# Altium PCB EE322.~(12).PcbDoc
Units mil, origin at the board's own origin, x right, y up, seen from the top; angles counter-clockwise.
Board outline 6000 x 4000 mil, 2 copper layers (Top Layer, Bottom Layer); 45 components, 23 nets, 107 pads, 0 vias.
Unrouted connection lines stored in the file: 78.
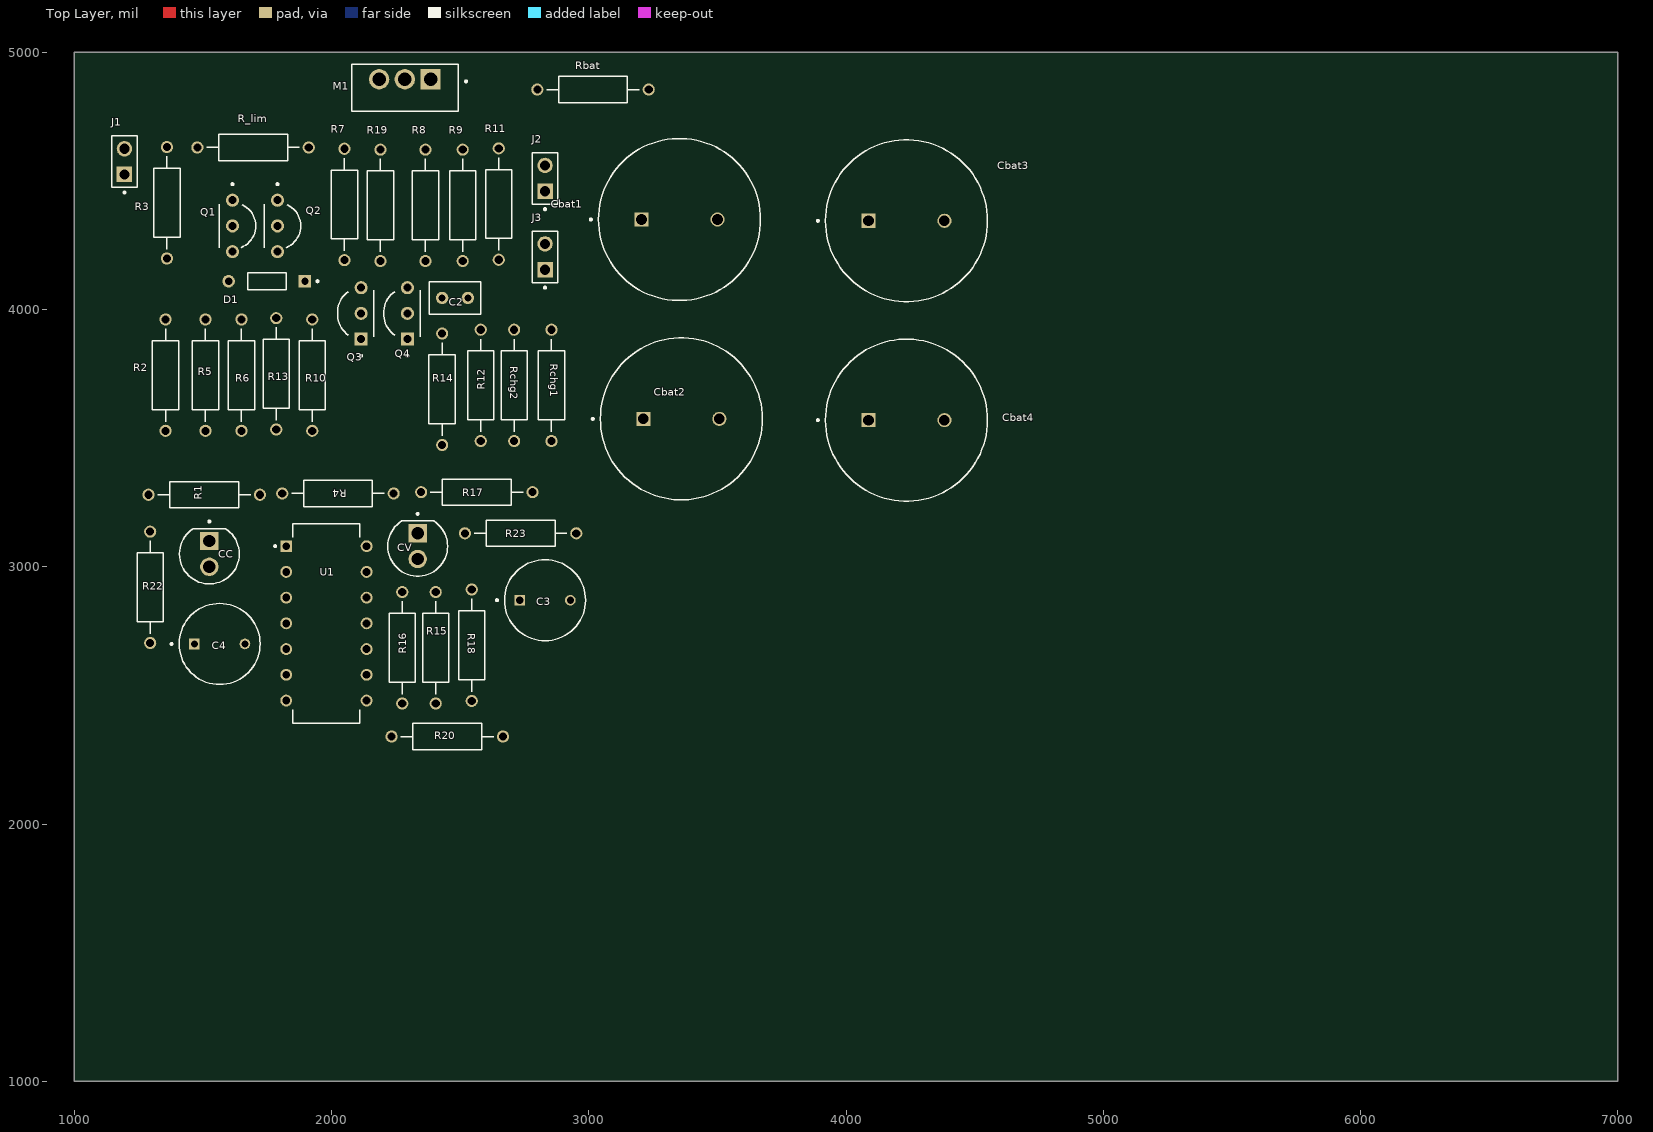
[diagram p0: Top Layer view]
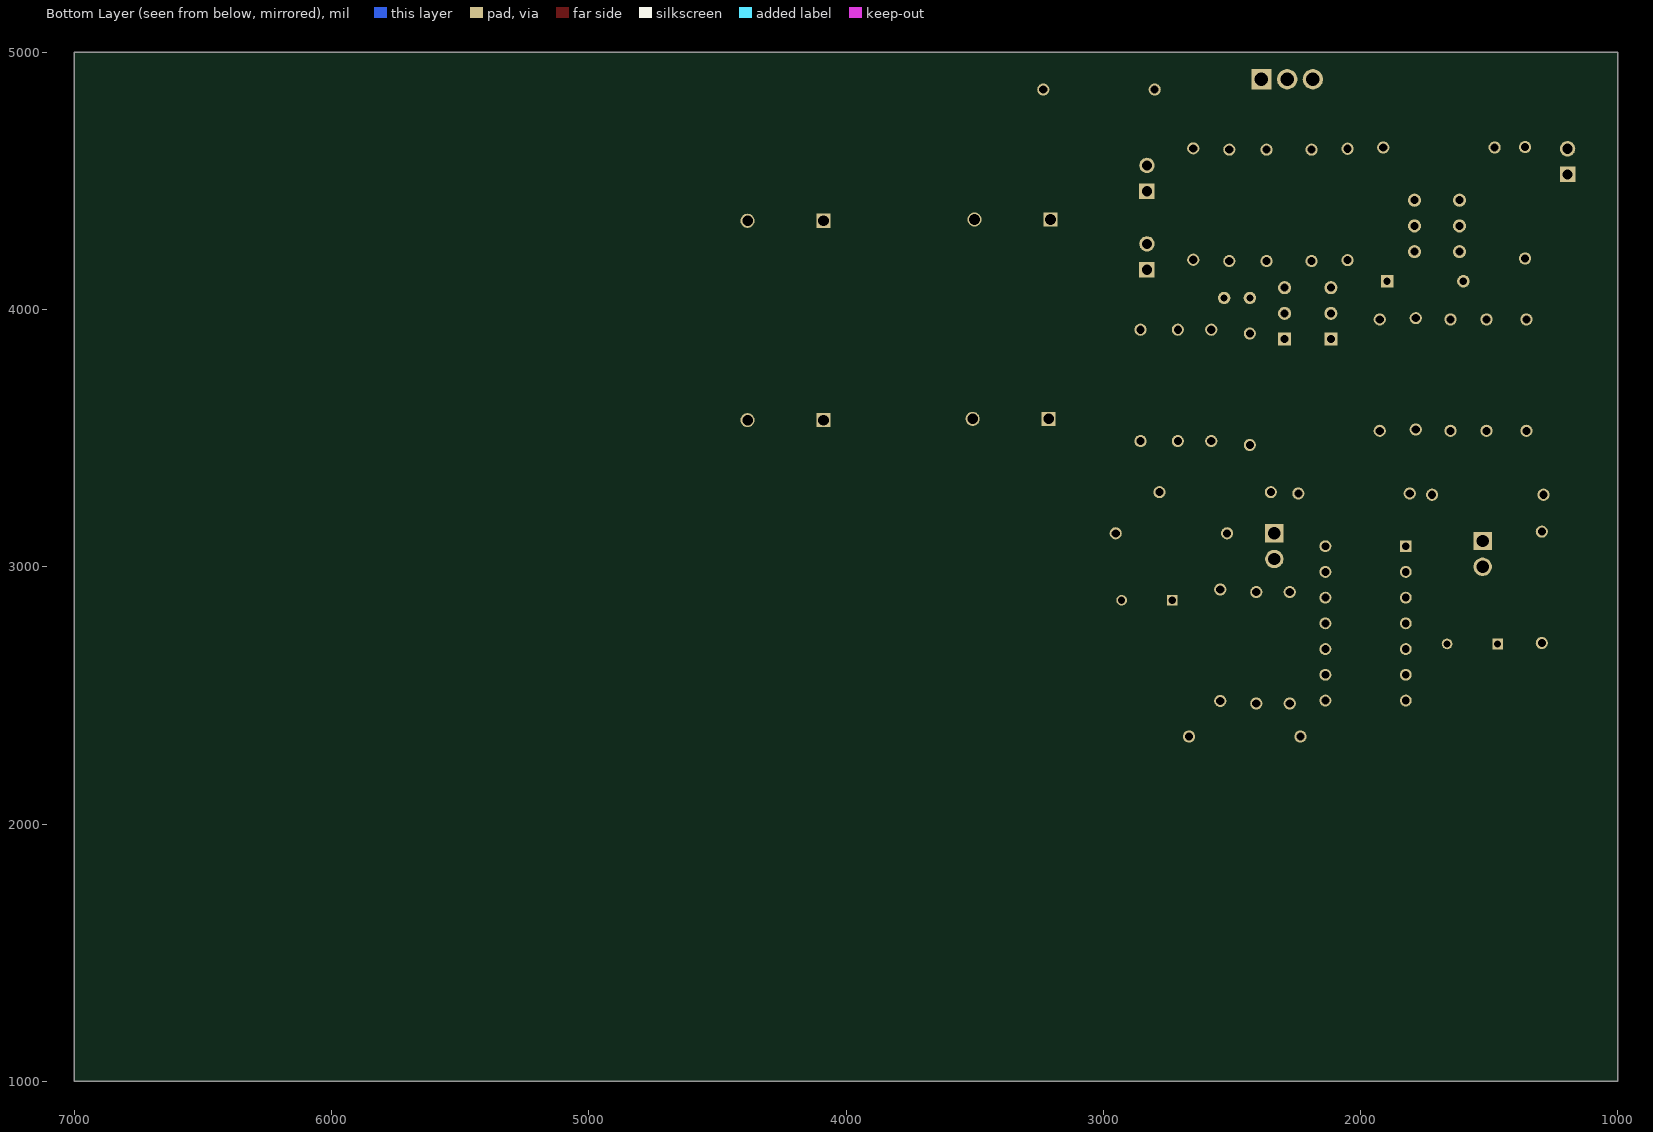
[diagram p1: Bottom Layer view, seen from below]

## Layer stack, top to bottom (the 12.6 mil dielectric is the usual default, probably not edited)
Top Solder: solder mask 0.4, Solder Resist, Dk 3.5
Top Layer: signal copper 1.4
Dielectric 1: dielectric 12.6, FR-4, Dk 4.8
Bottom Layer: signal copper 1.4
Bottom Solder: solder mask 0.4, Solder Resist, Dk 3.5

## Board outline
1000,1000 7000,1000 7000,5000 1000,5000

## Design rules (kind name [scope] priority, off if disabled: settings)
Clearance [All] p1: gap=10 ignorepadtopadclearanceinfootprint=FALSE
Height [All] p1: minheight=0 maxheight=1500 prefheight=500
PolygonConnect [All] p1: connectstyle=Relief reliefconductorwidth=10 reliefentries=4 polygonreliefangle="90 Angle" airgapwidth=10
RoutingVias [All] p1: holewidth=28 width=50 viastyle="Through Hole" minholewidth=28 minwidth=50 maxholewidth=28 maxwidth=50
SilkToSolderMaskClearance [IsPad] p1: minsilkscreentomaskgap=9 clearancetoexposedcopper=TRUE
SolderMaskExpansion [All] p1: expansion=0 istentingtop=FALSE
Width [All] p1: maxlimit=40 minlimit=20 preferedwidth=20
28 further rules are at their usual default settings.

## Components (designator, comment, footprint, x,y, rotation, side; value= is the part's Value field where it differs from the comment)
C2 "" CAPRR254W50L508T317H508 2480,4045 r0 top
C3 "ECEA1HKA330Q" CAPPRD500W45D800H700 2830,2870 r0 top
C4 "ECEA1HKA330Q" CAPPRD500W45D800H700 1565,2700 r0 top
Cbat1 "" CAPPRD750W80D1600H3150 3352.64,4350 r0 top
Cbat2 "" CAPPRD750W80D1600H3150 3360,3575 r0 top
Cbat3 "" CAPPRD750W80D1600H3150 4235,4345 r0 top
Cbat4 "" CAPPRD750W80D1600H3150 4235,3570 r0 top
CC "" LEDRD254W57D500H1070 1525,3050 r270 top
CV "" LEDRD254W57D500H1070 2335,3080 r270 top
D1 "1N4148" DIOAD753W49L380D172B 1748.37,4110 r180 top
J1 "" CONNFLY_DS1021-1X2SF11-B 1195,4575 r90 top
J2 "" CONNFLY_DS1021-1X2SF11-B 2830,4510 r90 top
J3 "" CONNFLY_DS1021-1X2SF11-B 2830,4205 r90 top
M1 "" TO254P1052X465X1989-3 2385,4895 r180 top
Q1 "" TO92254P460H750-3#1 1615,4325 r270 top
Q2 "" TO92254P460H750-3#1 1790,4325 r270 top
Q3 "" TO92254P460H750-3#2 2115,3985 r90 top
Q4 "" TO92254P460H750-3#2 2295,3985 r90 top
R1 "" RESAD1100W55L680D260 1505,3280 r180 top
R2 "" RESAD1100W55L680D260 1355,3745 r90 top
R3 "" RESAD1100W55L680D260 1360,4415 r90 top
R4 "" RESAD1100W55L680D260 2025,3285 r180 top
R5 "" RESAD1100W55L680D260 1510,3745 r90 top
R6 "" RESAD1100W55L680D260 1650,3745 r90 top
R7 "" RESAD1100W55L680D260 2050,4408.46 r90 top
R8 "" RESAD1100W55L680D260 2365,4405 r90 top
R9 "" RESAD1100W55L680D260 2510,4405 r90 top
R10 "" RESAD1100W55L680D260 1925,3745 r270 top
R11 "" RESAD1100W55L680D260 2650,4410 r90 top
R12 "" RESAD1100W55L680D260 2580,3705 r90 top
R13 "" RESAD1100W55L680D260 1785,3750 r90 top
R14 "" RESAD1100W55L680D260 2430,3690 r270 top
R15 "MFR-25FBF52-10K" RESAD1100W55L680D260 2405,2685 r90 top
R16 "MFR-25FBF52-10K" RESAD1100W55L680D260 2275,2685 r270 top
R17 "MFR-25FBF52-10K" RESAD1100W55L680D260 2565,3290 r180 top
R18 "MFR-25FBF52-10K" RESAD1100W55L680D260 2545,2695 r90 top
R19 "" RESAD1100W55L680D260 2190,4405 r90 top
R20 "MFR-25FBF52-10K" RESAD1100W55L680D260 2450,2340 r0 top
R22 "" RESAD1100W55L680D260 1295,2920 r90 top
R23 "" RESAD1100W55L680D260 2735,3130 r0 top
R_lim "" RESAD1100W55L680D260 1695,4630 r0 top
Rbat "" RESAD1100W55L680D260 3016.54,4855 r180 top
Rchg1 "" RESAD1100W55L680D260 2855,3705 r270 top
Rchg2 "" RESAD1100W55L680D260 2710,3705 r270 top
U1 "LM339AN" DIP794W45P254L1969H508Q14 1980,2780 r0 top

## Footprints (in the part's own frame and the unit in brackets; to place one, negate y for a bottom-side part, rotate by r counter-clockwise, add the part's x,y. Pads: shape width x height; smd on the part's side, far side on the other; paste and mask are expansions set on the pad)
CAPPRD500W45D800H700 [mm]
  round 1.05 hole 0.7: N(2.5,0)
  rect 1.05x1.05 / inner round 1.05 / far side rect 1.05x1.05 hole 0.7: P(-2.5,0)
  silkscreen extent -4.85,-4 4,4, body extent -4,-4 4,4, height 7
CAPPRD750W80D1600H3150 [mm]
  round 1.4 hole 1.05: N(3.75,0)
  rect 1.4x1.4 hole 1.05: P(-3.75,0)
  silkscreen extent -8.85,-8 8,8, body extent -8,-8 8,8, height 31.5
CAPRR254W50L508T317H508 [mm]
  round 1.218 hole 0.71: 1(-1.27,0) 2(1.27,0)
  silkscreen extent -2.54,-1.59 2.54,1.59
CONNFLY_DS1021-1X2SF11-B [mm]
  rect 1.53x1.53 / inner round 1.53 / far side rect 1.53x1.53 hole 1.02 mask+0.102: 1(-1.27,0)
  round 1.53 hole 1.02 mask+0.102: 2(1.27,0)
  silkscreen extent -3.15,-1.25 2.54,1.25, body extent -2.54,-1.25 2.54,1.25, height 8.6
DIOAD753W49L380D172B [mm]
  round 1.238 hole 0.73 mask+0.102: A(3.768,0)
  rect 1.238x1.238 / inner round 1.238 / far side rect 1.238x1.238 hole 0.73 mask+0.102: K(-3.768,0)
  silkscreen extent -5.1,-0.86 1.9,0.86
DIP794W45P254L1969H508Q14 [mm]
  rect 1.17x1.17 / inner round 1.17 / far side rect 1.17x1.17 hole 0.77 mask+0.102: 1(-3.97,7.62)
  round 1.17 hole 0.77 mask+0.102: 2(-3.97,5.08) 3(-3.97,2.54) 4(-3.97,0) 5(-3.97,-2.54) 6(-3.97,-5.08) 7(-3.97,-7.62) 8(3.97,-7.62) 9(3.97,-5.08) 10(3.97,-2.54) 11(3.97,0) 12(3.97,2.54) 13(3.97,5.08) 14(3.97,7.62)
  silkscreen extent -5.15,-9.84 3.3,9.84, body extent -3.94,-9.65 3.94,9.65, height 5.08
LEDRD254W57D500H1070 [mm]
  round 1.815 hole 1.21: A(1.27,0)
  rect 1.815x1.815 / inner round 1.815 / far side rect 1.815x1.815 hole 1.21: C(-1.27,0)
  silkscreen extent -3.3,-2.96 2.96,2.96, body extent -2.6,-2.95 2.95,2.95, height 9.1
RESAD1100W55L680D260 [mm]
  round 1.2 hole 0.8: 1(-5.5,0) 2(5.5,0)
  silkscreen extent -4.58,-1.3 4.58,1.3, body extent -5.77,-1.2 5.77,1.2, height 2.4
TO254P1052X465X1989-3 [mm]
  rect 2.01x2.01 / inner round 2.01 / far side rect 2.01x2.01 hole 1.34: 1(0,0)
  round 2.01 hole 1.34: 2(2.54,0) 3(5.08,0)
  silkscreen extent -3.6,-1.5 7.8,3.16, body extent -5.12,-1.54 5.12,2.91, height 19.89
TO92254P460H750-3#1 [mm]
  round 1.298 hole 0.79 mask+0.102: 1(-2.54,0) 2(0,0) 3(2.54,0)
  silkscreen extent -4.22,-1.3 2.15,2.3, body extent -2.74,-1.27 2.74,2.33, height 8.09
TO92254P460H750-3#2 [mm]
  rect 1.298x1.298 / inner round 1.298 / far side rect 1.298x1.298 hole 0.79 mask+0.102: 1(-2.54,0)
  round 1.298 hole 0.79 mask+0.102: 2(0,0) 3(2.54,0)
  silkscreen extent -4.29,-1.27 2.3,2.33, body extent -2.74,-1.27 2.74,2.33, height 8.09

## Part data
C2: library part SR291C104KAR, "SR Series 5.08 x 5.08 mm 100 nF 100 V Â±10 % Tol. X7R Radial Lead/SkyCapÂ®", Package=None
C3 C4: "CAP ALUM 33UF 20% 50V RADIAL", Package="RADIAL-2 Panasonic"
Cbat1 Cbat2 Cbat3 Cbat4: library part ECA1HHG222, "Cap Aluminum 2200uF 50V 20% (16 X 31.5mm) Radial Aluminum Cylindrical Can 7.5mm 1470mA 2000 hr 105C Bulk", Package="RADIAL-2 Panasonic"
CC CV: library part L08R5000Q1, "LED, 5MM, ORANGE; LED / Lamp Size: 5mm / T-1 3/4; LED Colour: Orange; Typ Luminous Intensity: 4.3mcd; Viewing Angle: ...", Package=None
D1: "Diode Standard 75V 200mA Surface Mount SOD-523F", Package="AXIAL LEAD-2 ON Semiconductor"
J1 J2 J3: library part DS1021-1X2SF11-B, "2 position 2.54mm single row vertical pin header", Package=None
M1: library part IRF9540, "P-Channel 100 V 19A (Tc) 3.7W (Ta), 150W (Tc) Surface Mount DÂ²PAK (TO-263)", Package="TO-220-3 Vishay"
Q1 Q2: library part 2N3906, "BJT, TO-92, 40V, 200mA, PNP, 0.625W, 150Â°C", Package="TO-92 Diotec"
Q3 Q4: library part 2N3904, "BJT, TO-92, 40V, 200mA, NPN, 0.625W, 150Â°C", Package="TO-92 Diotec"
R1 R2 R3 R4 R5 R6 R7 R8 R9 R10 R11 R12 R13 R14 R19 R22 R23 R_lim Rbat Rchg1 Rchg2: library part MFR-25FBF52-10K, "10.2 kOhms Â±1% 0.25W, 1/4W Through Hole Resistor Axial - Metal Film", Package="RADIAL-2 YAGEO"
R15 R16 R17 R18 R20: "10.2 kOhms Â±1% 0.25W, 1/4W Through Hole Resistor Axial - Metal Film", Package="RADIAL-2 YAGEO"
U1: "Precision quad differential comparator, commercial grade", Package="PDIP-14 Texas Instruments"

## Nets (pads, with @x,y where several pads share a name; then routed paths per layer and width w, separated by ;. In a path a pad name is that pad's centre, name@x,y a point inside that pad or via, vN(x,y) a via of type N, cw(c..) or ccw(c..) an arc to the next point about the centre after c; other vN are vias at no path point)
gnd: C3.N C4.N Cbat1.N Cbat2.N Cbat3.N Cbat4.N J1.1 J3.2 R2.1 R5.1 R6.1 R10.1 R13.1 R16.1 R20.1 Rchg1.1 Rchg2.1 U1.12
NetC2_1: C2.1 D1.K M1.1 R9.2
NetC3_P: C3.P CV.C R4.1 U1.14
NetC4_P: C4.P CC.C R22.1 U1.1
NetCbat1_P: Cbat1.P Cbat2.P Cbat3.P Cbat4.P J2.1 J3.1 Rchg1.2 Rchg2.2
NetCC_A: CC.A R1.1
NetCV_A: CV.A R23.1
NetD1_A: D1.A Q1.3 R5.2
NetJ2_2: J2.2 Rbat.1
NetM1_3: M1.3 Q2.1 R7.2 R8.2 R_lim.2
NetQ1_1: Q1.1 R2.2 R3.1
NetQ1_2: Q1.2 Q2.2 Q2.3 R6.2
NetQ3_1: Q3.1 Q4.1 R10.2
NetQ3_2: Q3.2 Q4.2 R11.1 R13.2 R14.1
NetQ3_3: Q3.3 R19.1
NetQ4_3: Q4.3 R8.1 R9.1
NetR7_1: R7.1 R19.2
NetR12_1: R12.1 R14.2
NetR18_1: R18.1 R20.2
V1: R17.1 R18.2 U1.7 U1.8
V2: R15.1 R16.2 U1.6 U1.9
VBat: C2.2 M1.2 R12.2 R17.2 Rbat.2
vdd: J1.2 R1.2 R3.2 R4.2 R11.2 R15.2 R22.2 R23.2 R_lim.1 U1.3
pads on no net: U1.2 U1.4 U1.5 U1.10 U1.11 U1.13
